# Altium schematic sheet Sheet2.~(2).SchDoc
size A4
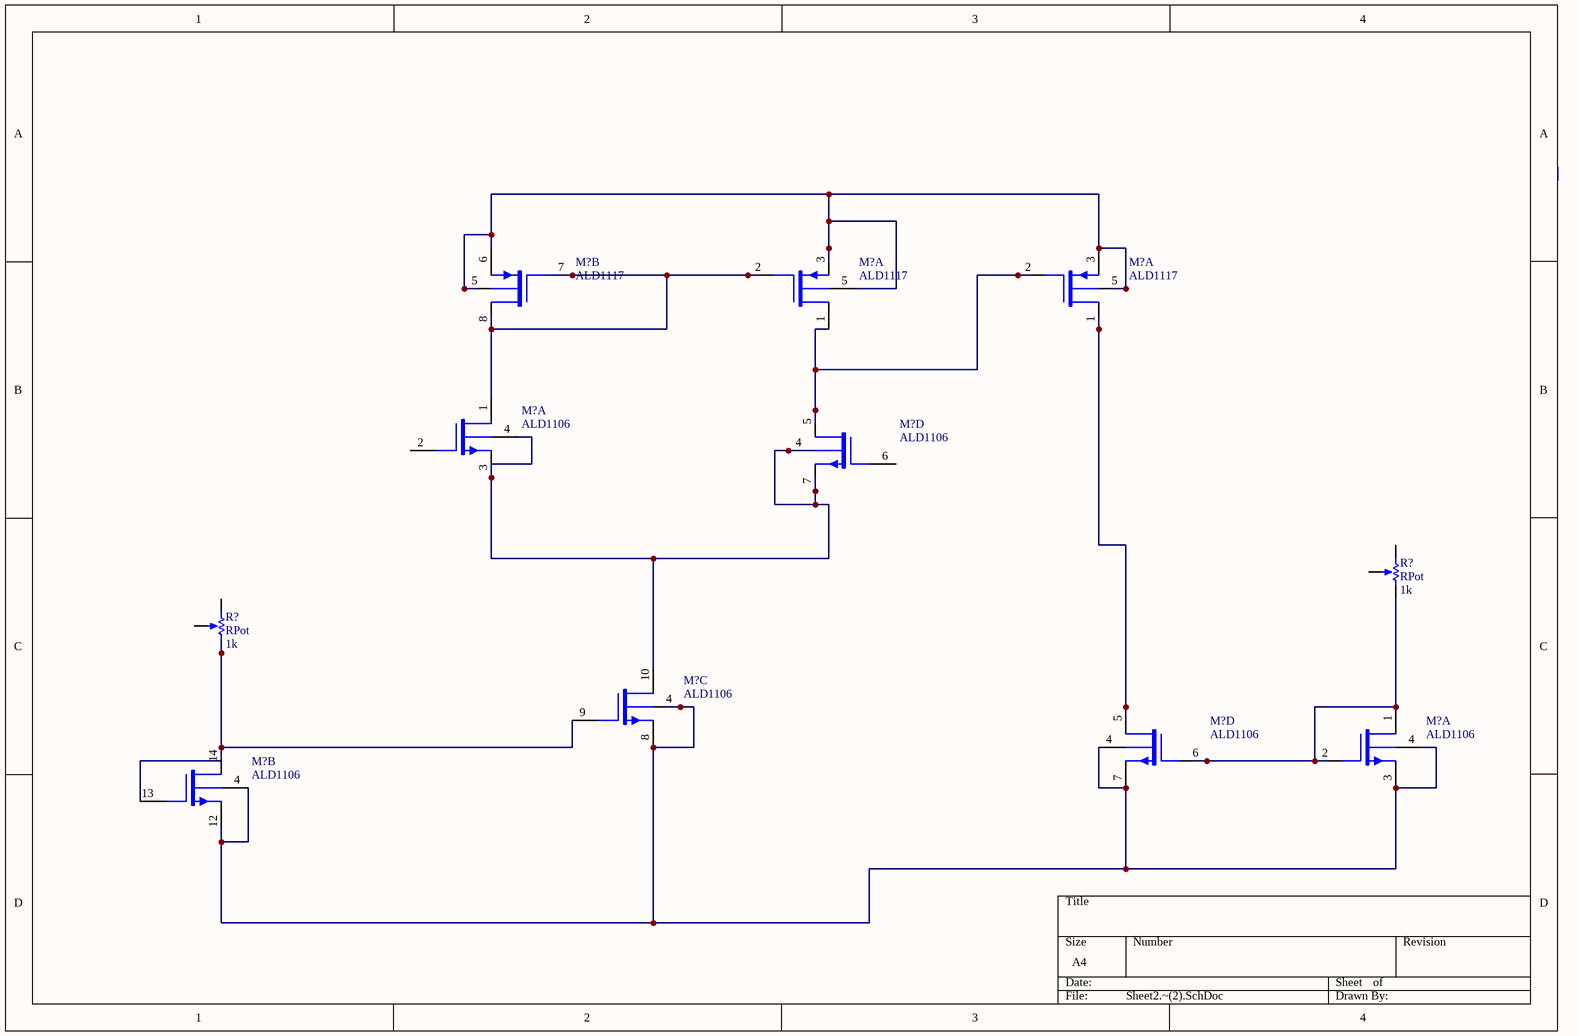
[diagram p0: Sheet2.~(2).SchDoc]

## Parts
(Parts that share a designator on the sheet are numbered #1, #2 ... from top to bottom, then left to right.)
M?#1  ALD1117  [DIP-8]  (part B of 2)
M?#2  ALD1117  [DIP-8]  (part A of 2)
M?#3  ALD1117  [DIP-8]  (part A of 2)
M?#4  ALD1106  [DIP-14]  (part A of 4)
M?#5  ALD1106  [DIP-14]  (part D of 4)
M?#6  ALD1106  [DIP-14]  (part C of 4)
M?#7  ALD1106  [DIP-14]  (part D of 4)
M?#8  ALD1106  [DIP-14]  (part A of 4)
M?#9  ALD1106  [DIP-14]  (part B of 4)
R?#1  RPot  value 1k  [VR5]
R?#2  RPot  value 1k  [VR5]

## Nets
NetM?#1_5: M?#1.5(V+) M?#1.6(SP2) M?#2.3(SP1) M?#2.5(V+) M?#3.3(SP1) M?#3.5(V+)
NetM?#1_7: M?#1.7(GP2) M?#1.8(DP2) M?#2.2(GP1) M?#4.1(DN1)
NetM?#2_1: M?#2.1(DP1) M?#3.2(GP1) M?#5.5(DN4)
NetM?#3_1: M?#3.1(DP1) M?#7.5(DN4)
NetM?#4_3: M?#4.3(SN1) M?#4.4(V-) M?#5.4(V-) M?#5.7(SN4) M?#6.10(DN3)
NetM?#6_4: M?#6.4(V-) M?#6.8(SN3) M?#7.4(V-) M?#7.7(SN4) M?#8.3(SN1) M?#8.4(V-) M?#9.4(V-) M?#9.12(SN2)
NetM?#6_9: M?#6.9(GN3) M?#9.13(GN2) M?#9.14(DN2) R?#2.3(BOT)
NetM?#7_6: M?#7.6(GN4) M?#8.1(DN1) M?#8.2(GN1) R?#1.3(BOT)

Not connected (* = marked no-connect by the designer): M?#4 2(GN1); M?#5 6(GN4); R?#1 1(TOP) 2(TAP); R?#2 1(TOP) 2(TAP)

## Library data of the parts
M?#1-M?#3 = ALD1117: Dual P-channel matched MOSFET array
M?#4-M?#9 = ALD1106: Quad N-channel matched MOSFET array
R?#1 R?#2 = RPot: Potentiometer; Sim Note: Enter the Resistance value and the set point into parameter fields.; Set Position: 0.5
